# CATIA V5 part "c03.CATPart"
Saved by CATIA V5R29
Part number: c03
Source: Unknown
Bounding box of the stored display mesh (mm): x -38 to 35, y -200 to 200, z 50.137 to 235.137
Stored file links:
  C:\가치같이\SmartFactory_BoxErectorConveyor\Boxing(under)\c03.CATPart
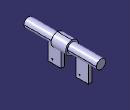
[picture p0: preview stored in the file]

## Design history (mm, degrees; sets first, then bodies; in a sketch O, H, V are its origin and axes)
Body1 (main body)
  Solid1 "PartBody": solid without history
